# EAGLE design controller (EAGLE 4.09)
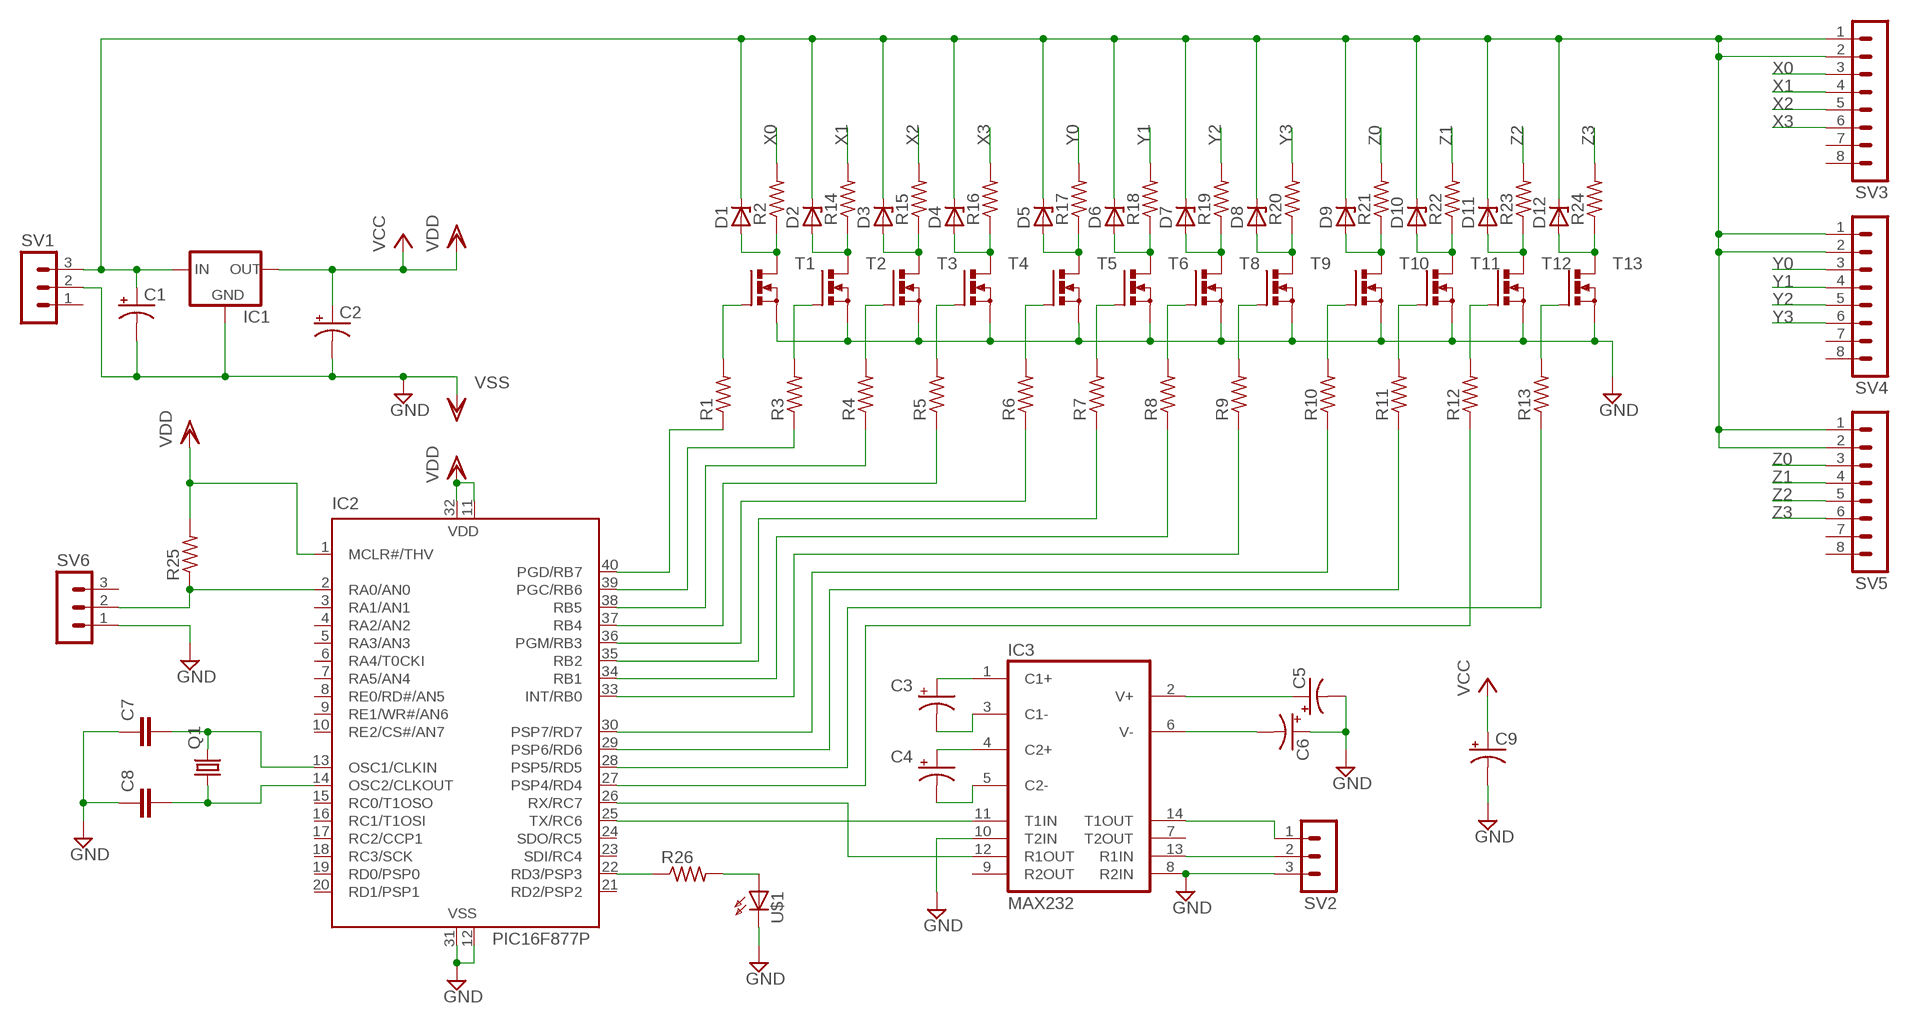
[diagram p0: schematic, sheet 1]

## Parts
C1  CPOL-USE7.5-16  [E7,5-16]
C2  CPOL-USB45181A  [B45181A]
C3  CPOL-USB45181A  [B45181A]
C4  CPOL-USB45181A  [B45181A]
C5  CPOL-USB45181A  [B45181A]
C6  CPOL-USB45181A  [B45181A]
C7  C5/2.5  [C5B2.5]
C8  C5/2.5  [C5B2.5]
C9  CPOL-USB45181B  [B45181B]
D1  ZENER-DIODEDO35Z10  [DO35Z10]
D2  ZENER-DIODEDO35Z10  [DO35Z10]
D3  ZENER-DIODEDO35Z10  [DO35Z10]
D4  ZENER-DIODEDO35Z10  [DO35Z10]
D5  ZENER-DIODEDO35Z10  [DO35Z10]
D6  ZENER-DIODEDO35Z10  [DO35Z10]
D7  ZENER-DIODEDO35Z10  [DO35Z10]
D8  ZENER-DIODEDO35Z10  [DO35Z10]
D9  ZENER-DIODEDO35Z10  [DO35Z10]
D10  ZENER-DIODEDO35Z10  [DO35Z10]
D11  ZENER-DIODEDO35Z10  [DO35Z10]
D12  ZENER-DIODEDO35Z10  [DO35Z10]
IC1  78XXS  [78XXS]
IC2  PIC16F877P  [DIL40]
IC3  MAX232  [DIL16]
Q1  CRYTALHC18U-V  [HC18U-V]
R1  R-US_0207/10  [0207/10]
R2  R-US_0922/22  [0922/22]
R3  R-US_0207/10  [0207/10]
R4  R-US_0207/10  [0207/10]
R5  R-US_0207/10  [0207/10]
R6  R-US_0207/10  [0207/10]
R7  R-US_0207/10  [0207/10]
R8  R-US_0207/10  [0207/10]
R9  R-US_0207/10  [0207/10]
R10  R-US_0207/10  [0207/10]
R11  R-US_0207/10  [0207/10]
R12  R-US_0207/10  [0207/10]
R13  R-US_0207/10  [0207/10]
R14  R-US_0922/22  [0922/22]
R15  R-US_0922/22  [0922/22]
R16  R-US_0922/22  [0922/22]
R17  R-US_0922/22  [0922/22]
R18  R-US_0922/22  [0922/22]
R19  R-US_0922/22  [0922/22]
R20  R-US_0922/22  [0922/22]
R21  R-US_0922/22  [0922/22]
R22  R-US_0922/22  [0922/22]
R23  R-US_0922/22  [0922/22]
R24  R-US_0922/22  [0922/22]
R25  R-US_0207/10  [0207/10]
R26  R-US_0207/10  [0207/10]
SV1  MA03-1  [MA03-1]
SV2  MA03-1  [MA03-1]
SV3  MA08-1  [MA08-1]
SV4  MA08-1  [MA08-1]
SV5  MA08-1  [MA08-1]
SV6  MA03-1  [MA03-1]
T1  PMOSFET_NTO220BV  [TO220BV]
T2  PMOSFET_NTO220BV  [TO220BV]
T3  PMOSFET_NTO220BV  [TO220BV]
T4  PMOSFET_NTO220BV  [TO220BV]
T5  PMOSFET_NTO220BV  [TO220BV]
T6  PMOSFET_NTO220BV  [TO220BV]
T8  PMOSFET_NTO220BV  [TO220BV]
T9  PMOSFET_NTO220BV  [TO220BV]
T10  PMOSFET_NTO220BV  [TO220BV]
T11  PMOSFET_NTO220BV  [TO220BV]
T12  PMOSFET_NTO220BV  [TO220BV]
T13  PMOSFET_NTO220BV  [TO220BV]
U$1  LEDSQR5.7X3.2  [U57X32]

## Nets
GND: C1.- C2.- C5.- C6.+ C7.1 C8.1 C9.- IC1.GND IC2.12(VSS) IC2.31(VSS) IC3.8(R2IN) IC3.10(T2IN) SV1.2 SV2.3 SV6.1 T1.S T2.S T3.S T4.S T5.S T6.S T8.S T9.S T10.S T11.S T12.S T13.S U$1.K(C) ; supply symbol labelled VSS
N$1: C1.+ D1.C D2.C D3.C D4.C D5.C D6.C D7.C D8.C D9.C D10.C D11.C D12.C IC1.IN SV1.3 SV3.1 SV3.2 SV4.1 SV4.2 SV5.1 SV5.2
N$2: C3.+ IC3.1(C1+)
N$3: C4.- IC3.5(C2-)
N$4: C4.+ IC3.4(C2+)
N$5: C3.- IC3.3(C1-)
N$6: IC2.25(TX/RC6) IC3.11(T1IN)
N$7: IC2.26(RX/RC7) IC3.12(R1OUT)
N$8: C5.+ IC3.2(V+)
N$9: C6.- IC3.6(V-)
N$10: R1.2 T1.G
N$11: IC3.13(R1IN) SV2.2
N$12: R3.2 T2.G
N$13: IC3.14(T1OUT) SV2.1
N$14: C7.2 IC2.13(OSC1/CLKIN) Q1.2
N$15: C8.2 IC2.14(OSC2/CLKOUT) Q1.1
N$16: R4.2 T3.G
N$17: R5.2 T4.G
N$18: R6.2 T5.G
N$19: R7.2 T6.G
N$20: R8.2 T8.G
N$21: R9.2 T9.G
N$22: R10.2 T10.G
N$23: R11.2 T11.G
N$24: R12.2 T12.G
N$25: R13.2 T13.G
N$26: IC2.40(PGD/RB7) R1.1
N$27: IC2.39(PGC/RB6) R3.1
N$28: IC2.38(RB5) R4.1
N$29: IC2.37(RB4) R5.1
N$30: IC2.36(PGM/RB3) R6.1
N$31: IC2.35(RB2) R7.1
N$32: IC2.34(RB1) R8.1
N$33: IC2.33(INT/RB0) R9.1
N$34: IC2.30(PSP7/RD7) R10.1
N$35: IC2.29(PSP6/RD6) R11.1
N$36: IC2.28(PSP5/RD5) R13.1
N$37: IC2.27(PSP4/RD4) R12.1
N$38: D1.A R2.1 T1.D
N$39: D2.A R14.1 T2.D
N$40: D3.A R15.1 T3.D
N$41: D4.A R16.1 T4.D
N$42: D5.A R17.1 T5.D
N$43: D6.A R18.1 T6.D
N$44: D7.A R19.1 T8.D
N$45: D8.A R20.1 T9.D
N$46: D9.A R21.1 T10.D
N$47: D10.A R22.1 T11.D
N$48: D11.A R23.1 T12.D
N$49: D12.A R24.1 T13.D
N$52: IC2.22(RD3/PSP3) R26.1
N$53: IC2.2(RA0/AN0) R25.1 SV6.2
N$54: R26.2 U$1.A
VCC: C2.+ C9.+ IC1.OUT IC2.1(MCLR#/THV) IC2.11(VDD) IC2.32(VDD) R25.2 ; supply symbol labelled VDD
X0: R2.2 SV3.3
X1: R14.2 SV3.4
X2: R15.2 SV3.5
X3: R16.2 SV3.6
Y0: R17.2 SV4.3
Y1: R18.2 SV4.4
Y2: R19.2 SV4.5
Y3: R20.2 SV4.6
Z0: R21.2 SV5.3
Z1: R22.2 SV5.4
Z2: R23.2 SV5.5
Z3: R24.2 SV5.6
Unconnected: IC2.3(RA1/AN1) IC2.4(RA2/AN2) IC2.5(RA3/AN3) IC2.6(RA4/T0CKI) IC2.7(RA5/AN4) IC2.8(RE0/RD#/AN5) IC2.9(RE1/WR#/AN6) IC2.10(RE2/CS#/AN7) IC2.15(RC0/T1OSO) IC2.16(RC1/T1OSI) IC2.17(RC2/CCP1) IC2.18(RC3/SCK) IC2.19(RD0/PSP0) IC2.20(RD1/PSP1) IC2.21(RD2/PSP2) IC2.23(SDI/RC4) IC2.24(SDO/RC5) IC3.7(T2OUT) IC3.9(R2OUT) SV1.1 SV3.7 SV3.8 SV4.7 SV4.8 SV5.7 SV5.8 SV6.3

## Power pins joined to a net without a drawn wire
GND: IC3.15(GND)
VCC: IC3.16(VCC)

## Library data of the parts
C1-C6 C9 = rcl:CPOL-US: POLARIZED CAPACITOR, American symbol
C7 C8 = capacitor-wima:C: CAPACITOR
D1-D12 = diode:ZENER-DIODE: Z-Diode
IC1 = v-reg:78XXS: VOLTAGE REGULATOR
IC2 = microchip:PIC16F87*: MICROCONTROLLER
IC3 = maxim:MAX232: RS232 TRANSEIVER
Q1 = crystal:CRYTAL: CRYSTAL
R1-R26 = rcl:R-US_: RESISTOR, American symbol
SV1 SV2 SV6 = con-lstb:MA03-1: PIN HEADER
SV3-SV5 = con-lstb:MA08-1: PIN HEADER
T1-T6 T8-T13 = transistor-power:PMOSFET_N: Power MOSFET N-Channel
U$1 = led:LED: LED

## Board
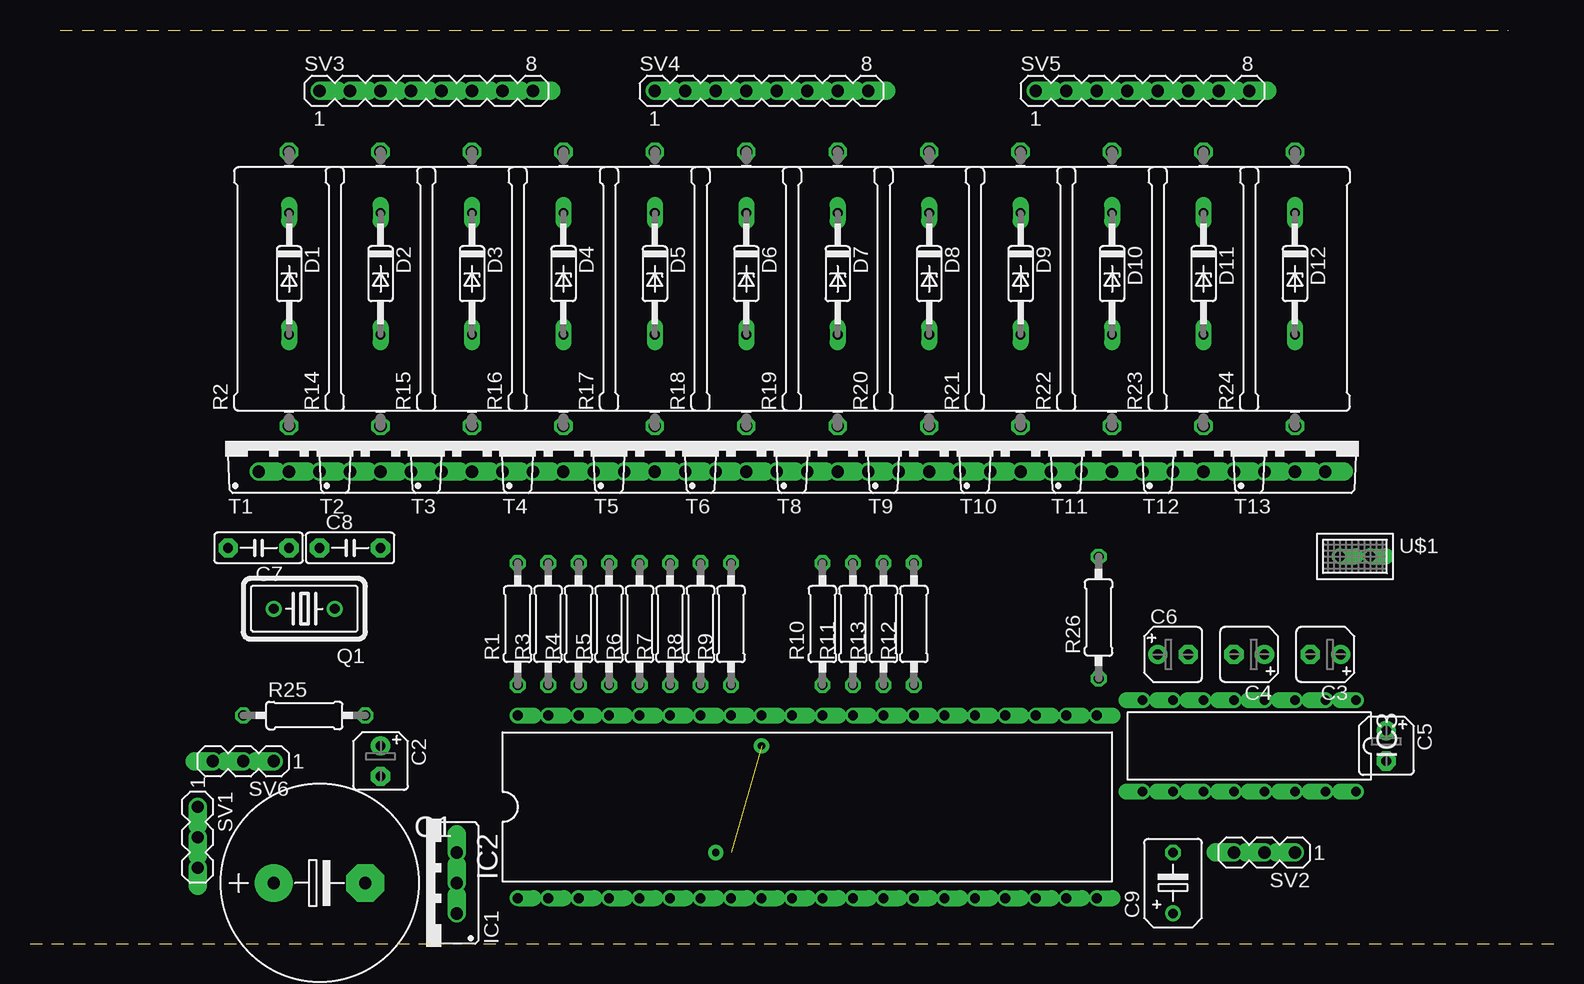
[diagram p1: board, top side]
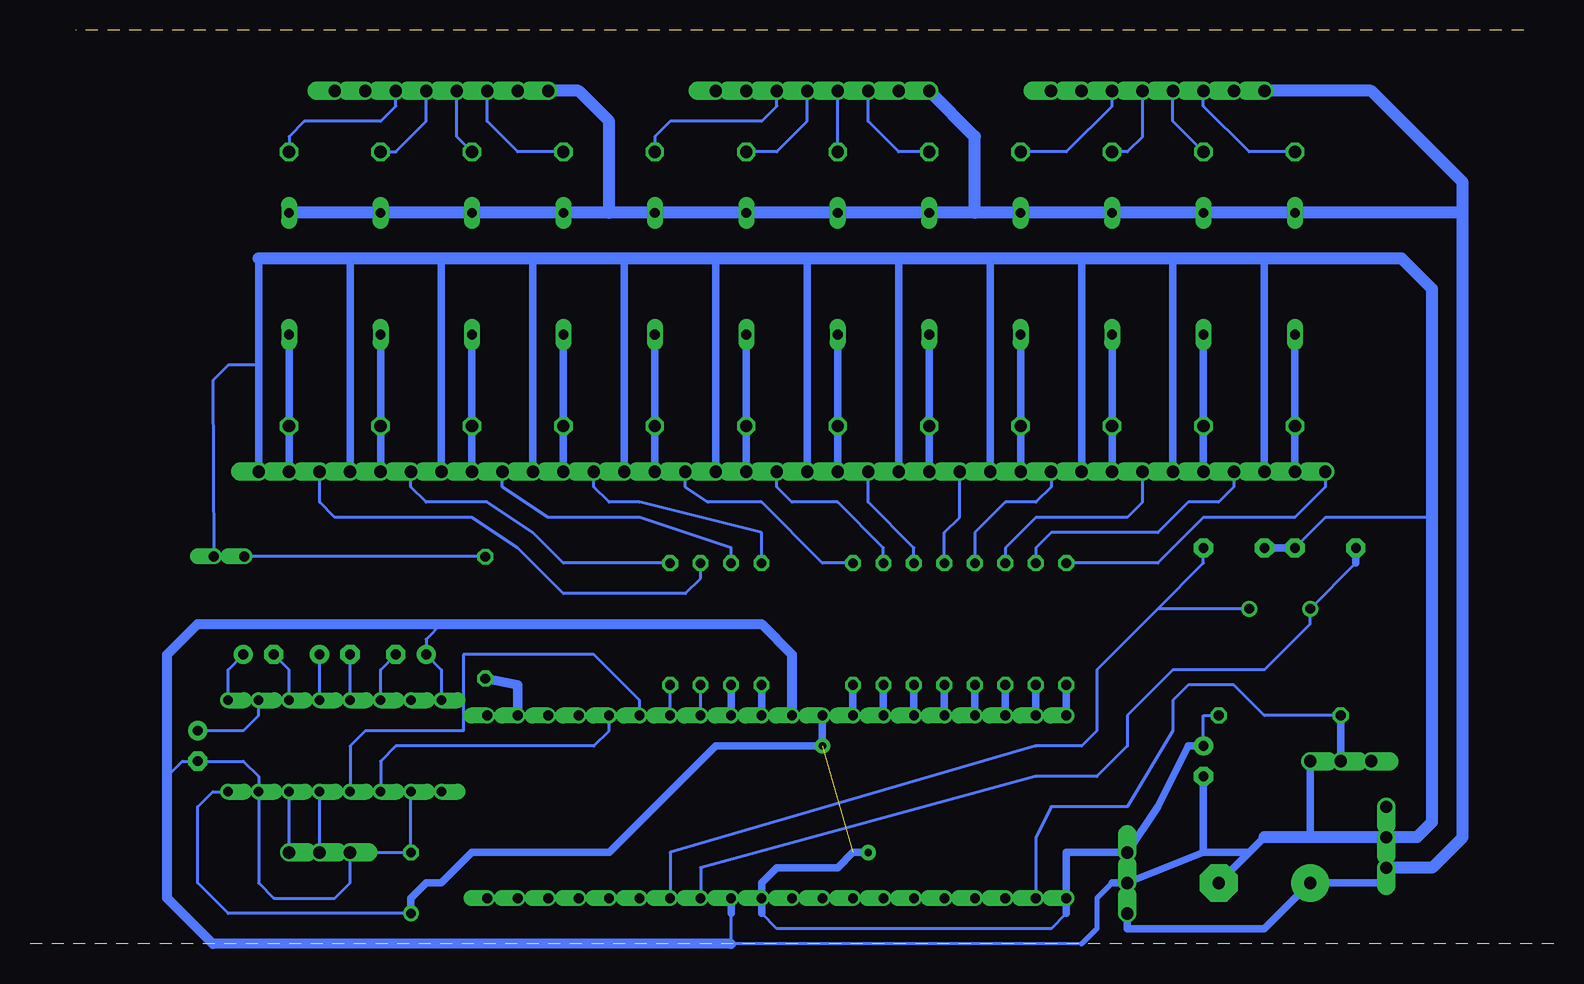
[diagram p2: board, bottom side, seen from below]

Size 127 x 76.2 mm. Coordinates in mm from the lower left corner, seen from the top.
Outline: 0,0 127,0
Outline: 2.54,76.2 123.19,76.2
Copper layers used: Bottom

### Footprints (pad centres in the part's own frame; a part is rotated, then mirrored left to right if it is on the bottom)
E7,5-16 = drill 1.016 pad 3.15 round: + -3.81,0 | drill 1.016 pad 3.15 octagon: - 3.81,0
B45181A = drill 0.813 pad 1.6 round: + -1.27,0 | drill 0.813 pad 1.6 octagon: - 1.27,0
C5B2.5 = drill 0.813 pad 1.6 octagon: 1 -2.54,0; 2 2.54,0
B45181B = drill 0.813 round: + -2.54,0 | drill 0.813 octagon: - 2.54,0
DO35Z10 = drill 0.813 long: A 5.08,0; C -5.08,0
78XXS = drill 1.016 offset: GND 0,-2.54; IN -2.54,-2.54; OUT 2.54,-2.54
DIL40 = drill 0.813 offset: 1 -24.13,-7.62; 2 -21.59,-7.62; 3 -19.05,-7.62; 4 -16.51,-7.62; 5 -13.97,-7.62; 6 -11.43,-7.62; 7 -8.89,-7.62; 8 -6.35,-7.62; 9 -3.81,-7.62; 10 -1.27,-7.62; 11 1.27,-7.62; 12 3.81,-7.62; 13 6.35,-7.62; 14 8.89,-7.62; 15 11.43,-7.62; 16 13.97,-7.62; 17 16.51,-7.62; 18 19.05,-7.62; 19 21.59,-7.62; 20 24.13,-7.62; 21 24.13,7.62; 22 21.59,7.62; 23 19.05,7.62; 24 16.51,7.62; 25 13.97,7.62; 26 11.43,7.62; 27 8.89,7.62; 28 6.35,7.62; 29 3.81,7.62; 30 1.27,7.62; 31 -1.27,7.62; 32 -3.81,7.62; 33 -6.35,7.62; 34 -8.89,7.62; 35 -11.43,7.62; 36 -13.97,7.62; 37 -16.51,7.62; 38 -19.05,7.62; 39 -21.59,7.62; 40 -24.13,7.62
DIL16 = drill 0.813 offset: 1 -8.89,-3.81; 2 -6.35,-3.81; 3 -3.81,-3.81; 4 -1.27,-3.81; 5 1.27,-3.81; 6 3.81,-3.81; 7 6.35,-3.81; 8 8.89,-3.81; 9 8.89,3.81; 10 6.35,3.81; 11 3.81,3.81; 12 1.27,3.81; 13 -1.27,3.81; 14 -3.81,3.81; 15 -6.35,3.81; 16 -8.89,3.81
HC18U-V = drill 0.813 round: 1 -2.54,0; 2 2.54,0
0207/10 = drill 0.813 octagon: 1 -5.08,0; 2 5.08,0
0922/22 = drill 1.016 octagon: 1 -11.43,0; 2 11.43,0
MA03-1 = drill 1.016 offset: 1 -2.54,0; 2 0,0; 3 2.54,0
MA08-1 = drill 1.016 offset: 1 -8.89,0; 2 -6.35,0; 3 -3.81,0; 4 -1.27,0; 5 1.27,0; 6 3.81,0; 7 6.35,0; 8 8.89,0
TO220BV = drill 1.016 offset: D 0,-2.54; G -2.54,-2.54; S 2.54,-2.54
U57X32 = drill 0.813 offset: A -1.27,0; K 1.27,0

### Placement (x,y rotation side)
C1  24.13,5.08 0 top
C2  29.21,15.24 270 top
C3  107.95,24.13 180 top
C4  101.6,24.13 180 top
C5  113.03,16.51 270 top
C6  95.25,24.13 0 top
C7  19.05,33.02 180 top
C8  26.67,33.02 0 top
C9  95.25,5.08 90 top
D1  21.59,55.88 270 top
D2  29.21,55.88 270 top
D3  36.83,55.88 270 top
D4  44.45,55.88 270 top
D5  52.07,55.88 270 top
D6  59.69,55.88 270 top
D7  67.31,55.88 270 top
D8  74.93,55.88 270 top
D9  82.55,55.88 270 top
D10  90.17,55.88 270 top
D11  97.79,55.88 270 top
D12  105.41,55.88 270 top
IC1  33.02,5.08 90 top
IC2  64.77,11.43 0 top
IC3  101.6,16.51 180 top
Q1  22.86,27.94 180 top
R1  40.64,26.67 90 top
R2  21.59,54.61 90 top
R3  43.18,26.67 90 top
R4  45.72,26.67 90 top
R5  48.26,26.67 90 top
R6  50.8,26.67 90 top
R7  53.34,26.67 90 top
R8  55.88,26.67 90 top
R9  58.42,26.67 90 top
R10  66.04,26.67 90 top
R11  68.58,26.67 90 top
R12  73.66,26.67 90 top
R13  71.12,26.67 90 top
R14  29.21,54.61 90 top
R15  36.83,54.61 90 top
R16  44.45,54.61 90 top
R17  52.07,54.61 90 top
R18  59.69,54.61 90 top
R19  67.31,54.61 90 top
R20  74.93,54.61 90 top
R21  82.55,54.61 90 top
R22  90.17,54.61 90 top
R23  97.79,54.61 90 top
R24  105.41,54.61 90 top
R25  22.86,19.05 0 top
R26  89.05,27.2 90 top
SV1  13.97,8.89 270 top
SV2  102.87,7.62 180 top
SV3  33.02,71.12 0 top
SV4  60.96,71.12 0 top
SV5  92.71,71.12 0 top
SV6  17.78,15.24 180 top
T1  21.59,41.91 0 top
T2  29.21,41.91 0 top
T3  36.83,41.91 0 top
T4  44.45,41.91 0 top
T5  52.07,41.91 0 top
T6  59.69,41.91 0 top
T8  67.31,41.91 0 top
T9  74.93,41.91 0 top
T10  82.55,41.91 0 top
T11  90.17,41.91 0 top
T12  97.79,41.91 0 top
T13  105.41,41.91 0 top
U$1  110.41,32.31 0 top

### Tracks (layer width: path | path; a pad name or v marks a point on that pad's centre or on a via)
GND
  Bottom 0.254: C7.1 19.05,35.56 10.16,35.56 | 39.37,0 68.58,0 IC2.12 | 107.95,48.26 110.49,48.26 111.76,46.99 U$1.K | IC3.10 C9.- SV2.3 100.33,5.08 101.6,3.81 106.68,3.81 107.95,5.08 IC3.15 107.95,13.97 109.22,15.24 C5.- 114.3,15.24 115.57,13.97 | IC3.8 92.71,22.86 C6.+ 93.98,25.4 92.71,26.67
  Bottom 0.406: 39.37,0 38.1,1.27 38.1,3.81 36.83,5.08
  Bottom 0.61: 11.43,8.89 SV1.2 20.32,8.89 SV6.1 | 24.13,57.15 T1.S | 31.75,57.15 T2.S | 100.33,57.15 T12.S | 85.09,57.15 T10.S | 77.47,57.15 T9.S | 69.85,57.15 T8.S | 62.23,57.15 T6.S | 54.61,57.15 T5.S | 46.99,57.15 T4.S | 39.37,57.15 T3.S | 25.4,7.62 C1.- | 24.13,8.89 25.4,7.62 | 25.4,7.62 29.21,7.62 | 29.21,7.62 C2.- | 29.21,7.62 IC1.GND 36.83,5.08 | C7.1 C8.1 | IC2.12 68.58,2.54 | 92.71,57.15 T11.S | 107.95,57.15 107.95,48.26 T13.S
  Bottom 0.813: IC2.31 63.5,24.13 66.04,26.67 92.71,26.67 113.03,26.67 115.57,24.13 115.57,13.97 115.57,3.81 111.76,0 68.58,0
  Bottom 1.016: 24.13,8.89 20.32,8.89 11.43,8.89 10.16,10.16 10.16,35.56 10.16,54.61 12.7,57.15 24.13,57.15 31.75,57.15 39.37,57.15 46.99,57.15 54.61,57.15 62.23,57.15 69.85,57.15 77.47,57.15 85.09,57.15 92.71,57.15 100.33,57.15 107.95,57.15
N$1
  Bottom 0.61: SV1.3 13.97,5.08 C1.+ 24.13,1.27 35.56,1.27 IC1.IN | D7.C D8.C | D6.C D7.C | D6.C D5.C 48.26,60.96 D4.C D3.C D2.C D1.C | D6.C D7.C | SV5.1 SV5.2
  Bottom 1.016: D12.C D11.C D10.C D9.C 78.74,60.96 | 48.26,60.96 D6.C D7.C D8.C 78.74,60.96 | SV4.2 SV4.1 48.26,67.31 48.26,60.96 | 48.26,60.96 D1.C 7.62,60.96 | 7.62,60.96 7.62,8.89 10.16,6.35 SV1.3 | 7.62,60.96 7.62,63.5 15.24,71.12 SV3.1 SV3.2 | SV5.1 81.28,71.12 78.74,68.58 78.74,60.96
N$2
  Bottom 0.254: IC3.1 110.49,22.86 C3.+
N$3
  Bottom 0.254: IC3.5 C4.-
N$4
  Bottom 0.254: IC3.4 C4.+
N$5
  Bottom 0.254: IC3.3 105.41,22.86 C3.-
N$6
  Bottom 0.254: IC2.25 78.74,17.78 80.01,16.51 96.52,16.51 97.79,15.24 IC3.11
N$7
  Bottom 0.254: IC2.26 76.2,20.32 80.01,24.13 90.88,24.13 90.88,17.78 99.06,17.78 100.33,16.51 IC3.12
N$8
  Bottom 0.254: IC3.2 107.95,19.05 109.22,17.78 C5.+
N$9
  Bottom 0.254: C6.- 97.79,22.86 IC3.6
N$10
  Bottom 0.254: T1.G 19.05,38.1 21.59,35.56 29.21,35.56 33.02,31.75 R1.2
N$11
  Bottom 0.254: SV2.2 IC3.13
N$12
  Bottom 0.254: T2.G 26.67,38.1 27.94,36.83 30.48,36.83 33.02,34.29 41.91,34.29 43.18,33.02 R3.2
N$13
  Bottom 0.254: SV2.1 IC3.14
N$14
  Bottom 0.254: IC2.13 71.12,6.35 43.18,13.97 38.1,13.97 35.56,16.51 35.56,19.05 31.75,22.86 24.13,22.86 20.32,26.67 Q1.2 16.51,31.75
  Bottom 0.61: 16.51,31.75 C7.2
N$15
  Bottom 0.254: IC2.14 73.66,7.62 43.18,16.51 39.37,16.51 38.1,17.78 38.1,22.86 33.02,27.94 | Q1.1 33.02,27.94 | C8.2 29.21,31.75 33.02,27.94
N$16
  Bottom 0.254: T3.G 34.29,36.83 35.56,35.56 43.18,35.56 45.72,33.02 R4.2
N$17
  Bottom 0.254: T4.G 41.91,38.1 43.18,36.83 45.72,36.83 48.26,34.29 R5.2
N$18
  Bottom 0.254: T5.G 49.53,35.56 50.8,34.29 R6.2
N$19
  Bottom 0.254: R7.2 53.34,33.02 57.15,36.83 T6.G
N$20
  Bottom 0.254: R8.2 55.88,33.02 59.69,36.83 63.5,36.83 64.77,38.1 T8.G
N$21
  Bottom 0.254: R9.2 60.96,31.75 66.04,36.83 70.51,36.83 72.39,38.1 T9.G
N$22
  Bottom 0.254: R10.2 66.04,34.29 76.2,36.83 78.74,36.83 80.01,38.1 T10.G
N$23
  Bottom 0.254: R11.2 68.58,33.02 76.2,35.56 83.82,35.56 87.63,38.1 T11.G
N$24
  Bottom 0.254: R12.2 82.55,31.75 85.09,34.29 88.9,36.83 93.98,36.83 95.25,38.1 T12.G
N$25
  Bottom 0.254: R13.2 71.12,30.48 72.39,29.21 82.55,29.21 86.36,33.02 90.17,35.56 101.6,35.56 102.87,36.83 T13.G
N$26
  Bottom 0.61: IC2.40 R1.1
N$27
  Bottom 0.61: IC2.39 R3.1
N$28
  Bottom 0.61: IC2.38 R4.1
N$29
  Bottom 0.61: IC2.37 R5.1
N$30
  Bottom 0.61: IC2.36 R6.1
N$31
  Bottom 0.61: IC2.35 R7.1
N$32
  Bottom 0.61: IC2.34 R8.1
N$33
  Bottom 0.61: IC2.33 R9.1
N$34
  Bottom 0.61: IC2.30 R10.1
N$35
  Bottom 0.61: IC2.29 R11.1
N$36
  Bottom 0.254: IC2.28 R13.1
N$37
  Bottom 0.254: IC2.27 R12.1
N$38
  Bottom 0.61: T1.D R2.1 D1.A T1.D
N$39
  Bottom 0.61: T2.D R14.1 | R14.1 D2.A | T2.D R14.1 | R14.1 D2.A | R14.1 D2.A | T2.D D2.A
N$40
  Bottom 0.61: T3.D R15.1 | R15.1 D3.A R15.1 | T3.D R15.1 | T3.D R15.1
N$41
  Bottom 0.61: T4.D R16.1 | R16.1 D4.A R16.1 | T4.D R16.1 | T4.D R16.1
N$42
  Bottom 0.61: R17.1 T5.D R17.1 | R17.1 D5.A
N$43
  Bottom 0.61: R18.1 T6.D D6.A
N$44
  Bottom 0.61: R19.1 T8.D R19.1 | R19.1 D7.A
N$45
  Bottom 0.61: R20.1 T9.D R20.1 | R20.1 D8.A
N$46
  Bottom 0.61: R21.1 T10.D R21.1 | R21.1 D9.A
N$47
  Bottom 0.61: T11.D R22.1 | R22.1 D10.A R22.1 | T11.D R22.1 | T11.D R22.1
N$48
  Bottom 0.61: R23.1 T12.D R23.1 | R23.1 D11.A
N$49
  Bottom 0.61: R24.1 T13.D R24.1 | R24.1 D12.A
N$52
  Bottom 0.8: IC2.22 86.36,21.59 R26.1
N$53
  Bottom 0.254: IC2.2 43.18,8.89 41.91,11.43 35.56,11.43 31.75,17.78 31.75,20.32 30.48,21.59 26.67,21.59 24.13,19.05 R25.1
  Bottom 0.61: SV6.2 R25.1
N$54
  Bottom 0.254: R26.2 U$1.A
VCC  (via drill 0.61 pad 1.27)  (1 unrouted)
  Bottom 0.254: 40.64,2.54 41.91,1.27 64.77,1.27 66.04,2.54 | R25.2 29.21,19.05 C2.+ | C9.+ 110.49,2.54 113.03,5.08 113.03,11.43 111.76,12.7 IC3.16
  Bottom 0.61: 40.64,2.54 IC2.1 40.64,7.62 IC1.OUT 33.02,11.43 30.48,16.51 C2.+ | 66.04,2.54 IC2.11 66.04,5.08 64.77,6.35 59.69,6.35 58.42,7.62 v57.15,7.62 | IC2.32 v60.96,16.51 69.85,16.51 78.74,7.62 90.17,7.62 92.71,5.08 93.98,5.08 95.25,3.81 C9.+
X0
  Bottom 0.254: R2.2 25.4,66.04 29.21,69.85 SV3.3
X1
  Bottom 0.254: R14.2 31.75,68.58 SV3.4
X2
  Bottom 0.254: R15.2 35.56,66.04 34.29,67.31 SV3.5
X3
  Bottom 0.254: R16.2 40.64,66.04 36.83,69.85 SV3.6
Y0
  Bottom 0.254: R17.2 54.61,66.04 57.15,68.58 SV4.3
Y1
  Bottom 0.254: R18.2 SV4.4
Y2
  Bottom 0.254: SV4.5 62.23,68.58 64.77,66.04 R19.2
Y3
  Bottom 0.254: SV4.6 64.77,69.85 66.04,68.58 73.66,68.58 74.93,67.31 R20.2
Z0
  Bottom 0.254: R21.2 86.36,66.04 88.9,68.58 SV5.3
Z1
  Bottom 0.254: R22.2 91.44,67.31 SV5.4
Z2
  Bottom 0.254: R23.2 96.52,66.04 93.98,68.58 SV5.5
Z3
  Bottom 0.254: SV5.6 96.52,69.85 97.79,68.58 104.14,68.58 105.41,67.31 R24.2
